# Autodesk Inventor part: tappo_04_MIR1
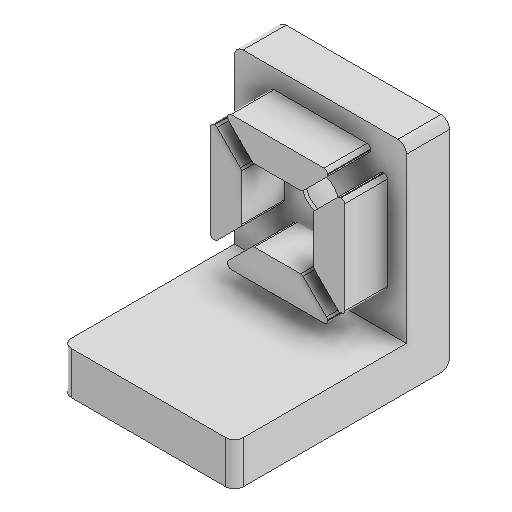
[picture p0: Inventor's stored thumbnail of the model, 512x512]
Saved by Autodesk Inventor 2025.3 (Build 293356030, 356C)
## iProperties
Created: 2026-02
Part Number: tappo_04_MIR1
Material: Generico
Document SubType Name: Modeling
Designer: R5800u
Density: 1 g/cm^3
Appearance: Default
Author: R5800u
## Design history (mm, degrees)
derived "tappo_04.ipt"
  sketch "Schizzo1"
    geometry: L1 (-10, 10)-(10, 10) reference; L2 (10, 10)-(10, -10) reference; L3 (10, -10)-(-10, -10) reference; L4 (-10, -10)-(-10, 10) reference; L5 (-10, 10)-(10, -10) reference; L6 (10, 10)-(-10, -10) reference; L7 (-6, -8)-(-3, -8) reference; L8 (-6, -7.061)-(-6, -8) reference; L9 (-2.939, -4)-(-6, -7.061) reference; L10 (0, 0)-(0, -10) reference; L11 (-2.939, -4)-(0, -4) reference; L12 (-3, -8)-(0, -8) reference; L13 (0, -7.8)-(-3, -7.8) reference; L14 (-3, -7.8)-(-5.8, -7.8) reference; L15 (-5.8, -7.8)-(-5.8, -7.144) reference; L16 (-5.8, -7.144)-(-2.856, -4.2) reference; L17 (-2.856, -4.2)-(0, -4.2) reference; L18 (0, -7.8)-(3, -7.8) reference; L19 (3, -7.8)-(5.8, -7.8) reference; L20 (5.8, -7.8)-(5.8, -7.144) reference; L21 (5.8, -7.144)-(2.856, -4.2) reference; L22 (2.856, -4.2)-(0, -4.2) reference
  sketch "Schizzo2"
    geometry: 1 further point
  sketch "Schizzo3"
    geometry: L1 (0, 0)-(-20, 0) reference; L2 (-20, 0)-(-20, 5) reference; L3 (0, 5)-(-20, 5) reference; L4 (0, 0)-(0, 5) reference; 1 further point
  sketch "Schizzo4"
    geometry: L1 (10, -15)-(-10, -15) reference; L2 (10, 9)-(10, -15) reference; L3 (-10, -15)-(10, -15) reference; L4 (10, -15)-(10, -10.05) reference; L5 (10, -10.05)-(-10, -10.05) reference; L6 (-10, -10.05)-(-10, -15) reference; 1 further point
feature "Solido1::tappo_04.ipt"
feature "Solido2::tappo_04.ipt"
tag "Lavorazione contrassegno1"
node "Solido1"
node "Solido2"
